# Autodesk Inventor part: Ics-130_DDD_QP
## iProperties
Created: 2007-02
Part Number: Ics-130_DDD_QP
Checked By: Alves
Material: nicht zugewiesen
Description: XX BENENNUNG XX
Document SubType Name: Modellieren
Designer: Klein
ME: ST
Title: XX Gruppe XX
Author: Klein
Comments: keine Bemerkung
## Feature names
1. Grundkörper [Extrusion]
2. Grundkörperkontur [Extrusion]
3. Vertiefung [Extrusion]
4. 3 LED Fenster [Extrusion]
5. Sensoraufnahme [Extrusion]
6. Extrusion6
7. Drehung2 [Revolution]
8. Extrusion7
9. Rundung1 [Fillet]
10. Extrusion8
11. Extrusion9
12. Rundung2 [Fillet]
13. Drehung1 [Revolution]
